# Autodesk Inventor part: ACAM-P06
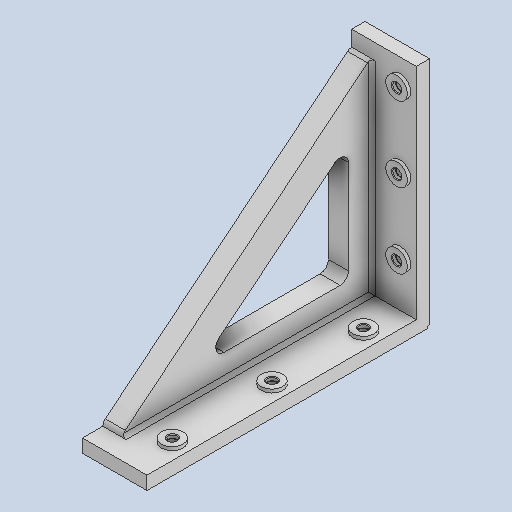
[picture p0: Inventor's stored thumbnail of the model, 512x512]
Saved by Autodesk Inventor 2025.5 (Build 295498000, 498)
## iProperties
Company: Open CASCADE
Created: 2026-10
Part Number: ACAM-P06
Material: Genérico
Description: Cartabón izquierdo
Document SubType Name: Modeling
Designer: Luis M
Authority: Unknown
Density: 1 g/cm^3
Appearance: Valor por defecto
Sending System: Open CASCADE 7.9
Preprocessor: Open CASCADE STEP processor 7.9
Material_BOM: PLA
Proceso_BOM: Impresión 3D
Title: Open CASCADE Shape Model
Author: Author
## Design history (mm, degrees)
feature "Base1"
node "Sólido1"
